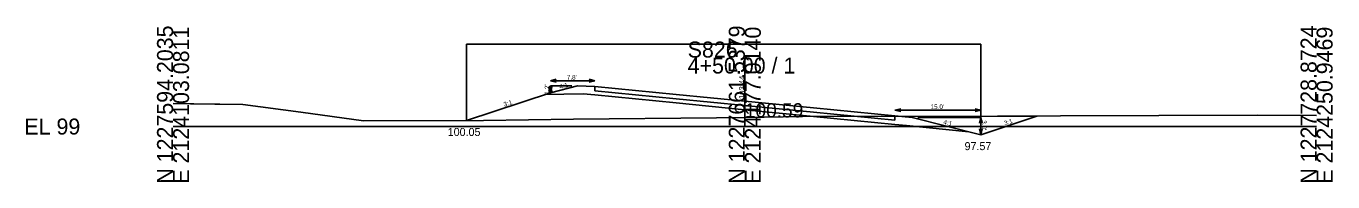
# Model space of a CAD drawing. Extents: x 2118382 to 2129610, y 1213030 to 1222578.
# Drawn here: x 2118381.9 to 2118610.4, y 1215030.1 to 1215057.4 of the extents above; entities that cross this region are included whole.
import ezdxf

# ---------------------------------------------------------------- set-up
doc = ezdxf.new("R2010")
doc.units = 0
for name, color, linetype in [('XS_CELL', 7, 'Continuous'), ('XS_M_DITCH', 7, 'Continuous'), ('XS_P_FINISHED_GRADE', 7, 'Continuous'), ('XS_P_FINISHED_GRADE_ELEV_TX', 7, 'Continuous'), ('XS_P_SUBGRADE_GRANULAR', 7, 'Continuous'), ('XS_P_SUBGRADE_PAVEMENT', 7, 'Continuous'), ('XS_P_TX_CLEARZONE', 7, 'Continuous'), ('XS_P_TX_DCH', 7, 'Continuous'), ('XS_P_TX_FS_BS', 7, 'Continuous'), ('XS_X_GROUND', 7, 'Continuous'), ('XS_X_GROUND_TX', 7, 'Continuous')]:
    doc.layers.add(name, color=color, linetype=linetype)

msp = doc.modelspace()

# ---------------------------------------------------------------- linework, layer by layer
at = {"layer": 'XS_CELL'}
for p, q in [((2118507.6, 1215039.8), (2118507.6, 1215051.88)), ((2118407.6, 1215039.8), (2118507.6, 1215039.8)), ((2118507.6, 1215039.8), (2118607.6, 1215039.8))]:
    msp.add_line(p, q, dxfattribs=at)
at = {"layer": 'XS_M_DITCH'}
for p, q in [((2118458.94, 1215040.85), (2118458.94, 1215054.25)), ((2118458.94, 1215054.25), (2118548.87, 1215054.25)), ((2118548.87, 1215054.25), (2118548.87, 1215038.37))]:
    msp.add_line(p, q, dxfattribs=at)
at = {"layer": 'XS_P_FINISHED_GRADE'}
for p, q in [((2118478.34, 1215046.91), (2118473.6, 1215045.73)), ((2118481.35, 1215046.83), (2118478.34, 1215046.91)), ((2118495.6, 1215045.43), (2118481.35, 1215046.83)), ((2118473.6, 1215045.73), (2118458.94, 1215040.85)), ((2118495.6, 1215045.43), (2118507.6, 1215044.25)), ((2118507.6, 1215044.25), (2118519.6, 1215043.07)), ((2118519.6, 1215043.07), (2118533.85, 1215041.67)), ((2118533.85, 1215041.67), (2118536.86, 1215041.37)), ((2118548.87, 1215038.37), (2118558.66, 1215041.63)), ((2118536.86, 1215041.37), (2118548.87, 1215038.37))]:
    msp.add_line(p, q, dxfattribs=at)
at = {"layer": 'XS_P_SUBGRADE_GRANULAR'}
for p, q in [((2118479.35, 1215045.53), (2118472.58, 1215045.39)), ((2118481.35, 1215045.33), (2118479.35, 1215045.53)), ((2118495.6, 1215043.93), (2118481.35, 1215045.33)), ((2118495.6, 1215043.93), (2118507.6, 1215042.75)), ((2118507.6, 1215042.75), (2118519.6, 1215041.57)), ((2118519.6, 1215041.57), (2118533.85, 1215040.17)), ((2118533.85, 1215040.17), (2118535.85, 1215039.97)), ((2118535.85, 1215039.97), (2118546.77, 1215038.9))]:
    msp.add_line(p, q, dxfattribs=at)
at = {"layer": 'XS_P_SUBGRADE_PAVEMENT'}
for p, q in [((2118481.35, 1215046.08), (2118481.35, 1215046.83)), ((2118495.6, 1215044.68), (2118481.35, 1215046.08)), ((2118495.6, 1215044.68), (2118507.6, 1215043.5)), ((2118507.6, 1215043.5), (2118519.6, 1215042.32)), ((2118519.6, 1215042.32), (2118533.85, 1215040.92)), ((2118533.85, 1215040.92), (2118533.85, 1215041.67))]:
    msp.add_line(p, q, dxfattribs=at)
at = {"layer": 'XS_P_TX_CLEARZONE'}
for p, q in [((2118473.6, 1215046.91), (2118473.35, 1215045.91)), ((2118473.6, 1215045.73), (2118473.35, 1215046.73)), ((2118473.6, 1215047.83), (2118474.6, 1215048.08)), ((2118473.6, 1215047.83), (2118474.6, 1215047.58)), ((2118481.35, 1215047.83), (2118473.6, 1215047.83)), ((2118473.6, 1215046.91), (2118473.85, 1215045.91)), ((2118473.6, 1215046.91), (2118473.6, 1215045.73)), ((2118477.34, 1215046.91), (2118473.6, 1215046.91)), ((2118473.6, 1215045.73), (2118473.85, 1215046.73)), ((2118481.35, 1215047.83), (2118480.35, 1215048.08)), ((2118481.35, 1215047.83), (2118480.35, 1215047.58)), ((2118533.85, 1215042.67), (2118534.86, 1215042.92)), ((2118533.85, 1215042.67), (2118534.86, 1215042.42)), ((2118533.85, 1215042.67), (2118548.87, 1215042.67)), ((2118548.87, 1215042.67), (2118547.87, 1215042.92)), ((2118548.87, 1215042.67), (2118547.87, 1215042.42)), ((2118537.86, 1215041.37), (2118548.87, 1215041.37)), ((2118548.87, 1215041.37), (2118548.62, 1215040.37)), ((2118548.87, 1215038.37), (2118548.62, 1215039.37)), ((2118548.87, 1215041.37), (2118548.87, 1215038.37)), ((2118548.87, 1215041.37), (2118549.12, 1215040.37)), ((2118548.87, 1215038.37), (2118549.12, 1215039.37))]:
    msp.add_line(p, q, dxfattribs=at)
at = {"layer": 'XS_X_GROUND'}
for p, q in [((2118407.6, 1215043.83), (2118410.64, 1215043.78)), ((2118410.64, 1215043.78), (2118411.21, 1215043.77)), ((2118411.21, 1215043.77), (2118414.94, 1215043.72)), ((2118414.94, 1215043.72), (2118415.79, 1215043.7)), ((2118415.79, 1215043.7), (2118419.83, 1215043.64)), ((2118419.83, 1215043.64), (2118429.96, 1215042.3)), ((2118429.96, 1215042.3), (2118440.91, 1215040.81)), ((2118507.6, 1215041.39), (2118517.68, 1215041.57)), ((2118517.68, 1215041.57), (2118551.82, 1215041.64)), ((2118551.82, 1215041.64), (2118558.15, 1215041.62)), ((2118558.15, 1215041.62), (2118562.83, 1215041.66)), ((2118562.83, 1215041.66), (2118597.23, 1215041.78)), ((2118597.23, 1215041.78), (2118607.6, 1215041.72)), ((2118440.91, 1215040.81), (2118461.87, 1215040.86)), ((2118461.87, 1215040.86), (2118477.62, 1215041.1)), ((2118477.62, 1215041.1), (2118502.67, 1215041.3)), ((2118502.67, 1215041.3), (2118507.6, 1215041.39))]:
    msp.add_line(p, q, dxfattribs=at)

# ---------------------------------------------------------------- texts
at = {"layer": 'XS_CELL'}
for s, p in [('N 1227594.2035', (2118407.6, 1215029.8)), ('E 2124103.0811', (2118410.4, 1215029.8)), ('N 1227661.5379', (2118507.6, 1215029.8)), ('E 2124177.0140', (2118510.4, 1215029.8)), ('N 1227728.8724', (2118607.6, 1215029.8)), ('E 2124250.9469', (2118610.4, 1215029.8))]:
    msp.add_text(s, height=2.8, rotation=90, dxfattribs=at).set_placement(p)
for s, p in [('S826', (2118497.6, 1215051.88)), ('4+50.00 / 1', (2118497.6, 1215049.08)), ('EL 99', (2118381.6, 1215038.4))]:
    msp.add_text(s, height=2.8, dxfattribs=at).set_placement(p)
at = {"layer": 'XS_P_FINISHED_GRADE_ELEV_TX'}
msp.add_text(' 103.44', height=1, rotation=90, dxfattribs=at).set_placement((2118507.6, 1215044.25))
at = {"layer": 'XS_P_TX_CLEARZONE'}
for s, p in [("7.8'", (2118476.47, 1215048.03)), ("15.0'", (2118540.09, 1215042.87))]:
    msp.add_text(s, height=0.8, dxfattribs=at).set_placement(p)
for s, rotation, p in [("1.2'", 90, (2118473.4, 1215045.43)), ("3.0'", 270, (2118549.07, 1215040.9))]:
    msp.add_text(s, height=0.8, rotation=rotation, dxfattribs=at).set_placement(p)
at = {"layer": 'XS_P_TX_DCH'}
for s, p in [('100.05', (2118455.64, 1215038.15)), ('97.57', (2118546.03, 1215035.67))]:
    msp.add_text(s, height=1.4, dxfattribs=at).set_placement(p)
at = {"layer": 'XS_P_TX_FS_BS'}
for s, rotation, p in [('4:1', 14.0217, (2118475.26, 1215046.35)), ('3:1', 18.4163, (2118465.56, 1215043.26)), ('4:1', 345.9814, (2118542.26, 1215040.23)), ('3:1', 18.4125, (2118553.06, 1215039.97))]:
    msp.add_text(s, height=0.8, rotation=rotation, dxfattribs=at).set_placement(p)
at = {"layer": 'XS_X_GROUND_TX'}
msp.add_text('100.59', height=2.5, dxfattribs=at).set_placement((2118507.6, 1215041.39))

doc.saveas('drawing.dxf')
